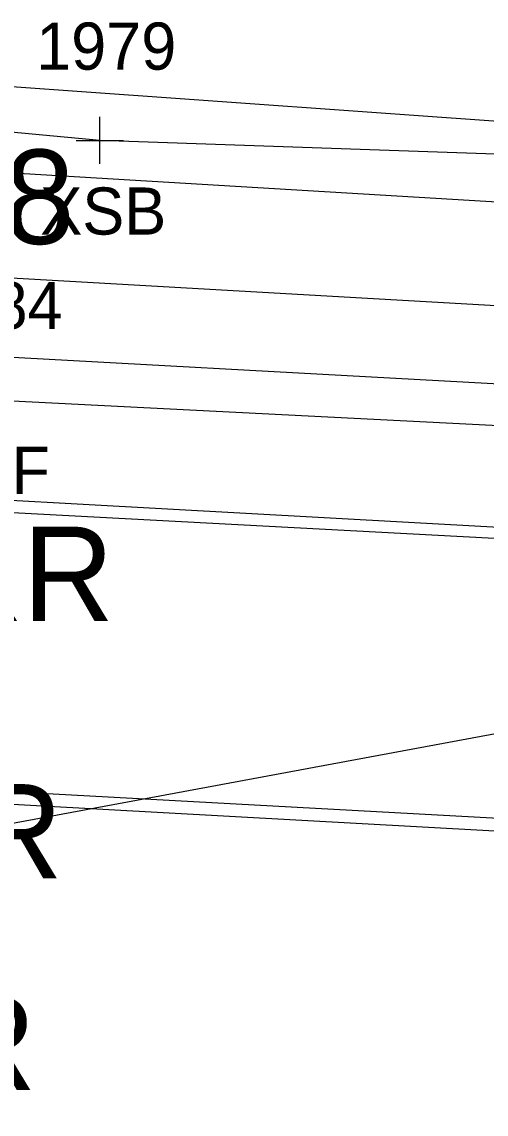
# Model space of a CAD drawing. Extents: x 1461855 to 1464118, y 556196 to 557441.
# Drawn here: x 1462156.07 to 1462165.93, y 556406.04 to 556429.22 of the extents above; entities that cross this region are included whole.
import ezdxf

# ---------------------------------------------------------------- set-up
doc = ezdxf.new("R2010")
doc.units = 0
for name, color, linetype in [('B_A', 7, 'Continuous'), ('B_I', 7, 'Continuous'), ('B_TIC', 7, 'Continuous'), ('BB', 7, 'Continuous'), ('BDEFAULT', 7, 'Continuous'), ('BELB', 7, 'Continuous'), ('BR', 7, 'Continuous'), ('L_A', 7, 'Continuous'), ('L_I', 7, 'Continuous'), ('LSOGP', 7, 'Continuous'), ('UW', 7, 'Continuous')]:
    doc.layers.add(name, color=color, linetype=linetype)

msp = doc.modelspace()

# ---------------------------------------------------------------- linework, layer by layer
at = {"layer": 'B_TIC'}
msp.add_line((1462157.73, 556426.705), (1462157.806, 556426.705), dxfattribs=at)
for points in [[(1462157.727, 556426.205), (1462157.727, 556427.205)], [(1462157.227, 556426.705), (1462158.227, 556426.705)]]:
    msp.add_lwpolyline(points, dxfattribs=at)
at = {"layer": 'BB'}
for points in [[(1462329.432, 556416.833), (1462323.508, 556417.23), (1462311.062, 556418.012), (1462310.913, 556418.032), (1462299.309, 556418.758), (1462286.726, 556419.548), (1462277.774, 556420.048), (1462264.748, 556420.883), (1462247.065, 556421.852), (1462234.884, 556422.524), (1462220.758, 556423.428), (1462206.908, 556424.316), (1462197.488, 556424.752), (1462189.82, 556425.214), (1462178.304, 556425.855), (1462168.167, 556426.338), (1462157.727, 556426.705), (1462150.543, 556427.374)], [(1462329.287, 556415.62), (1462150.452, 556426.331)]]:
    msp.add_lwpolyline(points, dxfattribs=at)
at = {"layer": 'BDEFAULT'}
for points in [[(1462339.234, 556413.311), (1462138.867, 556424.749)], [(1462328.804, 556412.4), (1462155.31, 556421.202)]]:
    msp.add_lwpolyline(points, dxfattribs=at)
at = {"layer": 'BELB'}
for points in [[(1462331.212, 556416.788), (1462304.91, 556418.948), (1462275.378, 556420.599), (1462239.194, 556422.631), (1462203.113, 556424.823), (1462173.724, 556426.567), (1462149.901, 556428.267), (1462148.306, 556426.947)], [(1462337.183, 556408.895), (1462260.894, 556413.183), (1462204.489, 556416.212), (1462146.838, 556419.281)], [(1462336.881, 556403.082), (1462260.891, 556407.332), (1462205.408, 556410.17), (1462146.764, 556413.378)]]:
    msp.add_lwpolyline(points, dxfattribs=at)
at = {"layer": 'BR'}
for points in [[(1462338.998, 556414.351), (1462338.8, 556409.121), (1462204.423, 556416.373), (1462146.886, 556419.56), (1462146.979, 556424.973)], [(1462356.157, 556401.791), (1462336.856, 556402.851), (1462260.866, 556407.054), (1462205.402, 556409.871), (1462146.909, 556413.108), (1462126.732, 556414.71), (1462111.281, 556416.663), (1462102.284, 556418.456)]]:
    msp.add_lwpolyline(points, dxfattribs=at)
at = {"layer": 'LSOGP'}
msp.add_lwpolyline([(1462020.074, 556368.854), (1462042.956, 556370.973), (1462054.408, 556366.714), (1462057.178, 556367.868), (1462065.942, 556367.888), (1462067.55, 556365.344), (1462103.87, 556357.158), (1462116.955, 556337.28), (1462130.508, 556327.239), (1462142.904, 556324.832), (1462154.863, 556328.185), (1462154.036, 556339.342), (1462154.572, 556350.205), (1462152.486, 556361.373), (1462151.238, 556373.266), (1462149.161, 556381.463), (1462150.123, 556395.584), (1462150.659, 556404.988), (1462152.286, 556411.553), (1462201.558, 556420.694)], dxfattribs=at)
at = {"layer": 'UW'}
msp.add_lwpolyline([(1462337.589, 556410.109), (1462335.376, 556410.001), (1462332.293, 556412.43), (1462148.132, 556422.524)], dxfattribs=at)

# ---------------------------------------------------------------- texts
at = {"layer": 'B_A'}
for s, p in [('XSB', (1462156.463, 556424.705)), ('XSF', (1462154.07, 556419.202))]:
    msp.add_text(s, height=1, dxfattribs=at).set_placement(p)
at = {"layer": 'B_I'}
for s, p in [('1979', (1462156.376, 556428.205)), ('1984', (1462153.963, 556422.702))]:
    msp.add_text(s, height=1, dxfattribs=at).set_placement(p)
at = {"layer": 'L_A'}
for p in [(1462150.447, 556416.507), (1462149.36, 556411.044), (1462148.798, 556406.553)]:
    msp.add_text('RVRR', height=2, dxfattribs=at).set_placement(p)
at = {"layer": 'L_I'}
msp.add_text('1958', height=2, dxfattribs=at).set_placement((1462151.243, 556424.507))

doc.saveas('drawing.dxf')
